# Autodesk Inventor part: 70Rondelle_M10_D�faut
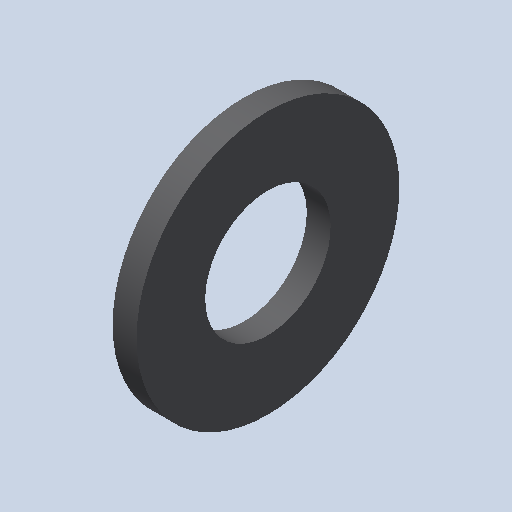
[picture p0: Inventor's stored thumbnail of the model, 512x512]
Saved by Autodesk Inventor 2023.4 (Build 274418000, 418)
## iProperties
Created: 2011-01
Part Number: 70Rondelle_M10_D�faut
Document SubType Name: Modeling
Designer: eric
Density: 1 g/cm^3
Mass: 0.587085 g
Surface Area: 7.91289 cm^2
Volume: 0.587085 cm^3
Material: Générique
Appearance: Blue
Author: eric
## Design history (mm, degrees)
feature "Base1"
node "Corps solides"
node "Corps surfaciques"
node "Solide1"
